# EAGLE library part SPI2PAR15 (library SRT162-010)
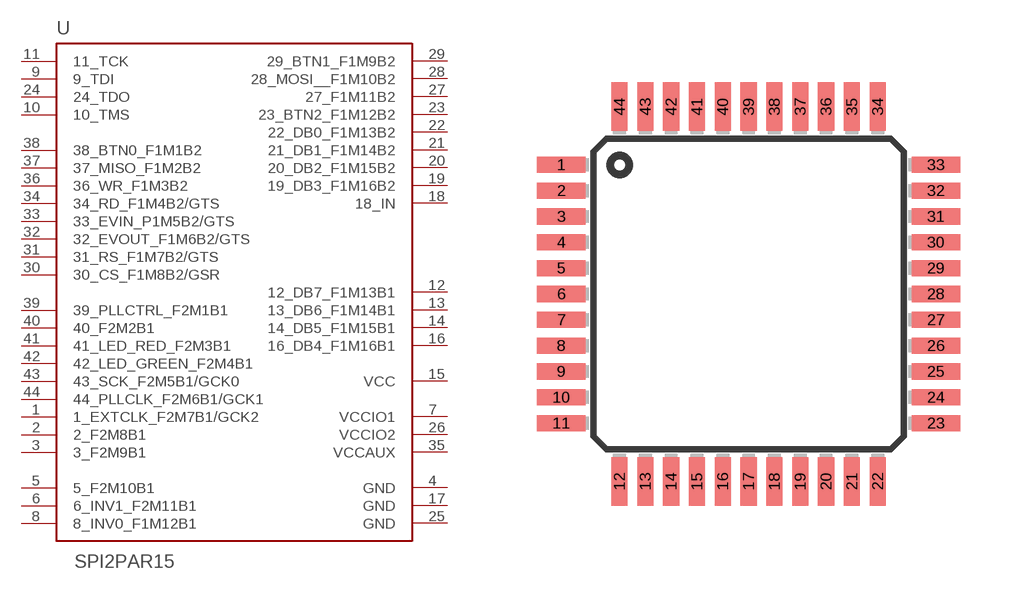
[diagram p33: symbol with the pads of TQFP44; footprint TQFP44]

Designator prefix -

## SPI2PAR15  [TQFP44]
1  1_EXTCLK_F2M7B1/GCK2
2  2_F2M8B1
3  3_F2M9B1
4  GND  pwr
5  5_F2M10B1
6  6_INV1_F2M11B1
7  VCCIO1  pwr
8  8_INV0_F1M12B1
9  9_TDI
10  10_TMS
11  11_TCK  in
12  12_DB7_F1M13B1
13  13_DB6_F1M14B1
14  14_DB5_F1M15B1
15  VCC  pwr
16  16_DB4_F1M16B1
17  GND  pwr
18  18_IN
19  19_DB3_F1M16B2
20  20_DB2_F1M15B2
21  21_DB1_F1M14B2
22  22_DB0_F1M13B2
23  23_BTN2_F1M12B2
24  24_TDO
25  GND  pwr
26  VCCIO2  pwr
27  27_F1M11B2
28  28_MOSI__F1M10B2
29  29_BTN1_F1M9B2
30  30_CS_F1M8B2/GSR
31  31_RS_F1M7B2/GTS
32  32_EVOUT_F1M6B2/GTS
33  33_EVIN_P1M5B2/GTS
34  34_RD_F1M4B2/GTS
35  VCCAUX  pwr
36  36_WR_F1M3B2
37  37_MISO_F1M2B2
38  38_BTN0_F1M1B2
39  39_PLLCTRL_F2M1B1
40  40_F2M2B1
41  41_LED_RED_F2M3B1
42  42_LED_GREEN_F2M4B1
43  43_SCK_F2M5B1/GCK0
44  44_PLLCLK_F2M6B1/GCK1

## Footprint TQFP44 (pad centres in mm)
smd 1.5 x 0.5: 1 -5.8,4; 2 -5.8,3.2; 3 -5.8,2.4; 4 -5.8,1.6; 5 -5.8,0.8; 6 -5.8,0; 7 -5.8,-0.8; 8 -5.8,-1.6; 9 -5.8,-2.4; 10 -5.8,-3.2; 11 -5.8,-4; 23 5.8,-4; 24 5.8,-3.2; 25 5.8,-2.4; 26 5.8,-1.6; 27 5.8,-0.8; 28 5.8,0; 29 5.8,0.8; 30 5.8,1.6; 31 5.8,2.4; 32 5.8,3.2; 33 5.8,4
smd 0.5 x 1.5: 12 -4,-5.8; 13 -3.2,-5.8; 14 -2.4,-5.8; 15 -1.6,-5.8; 16 -0.8,-5.8; 17 0,-5.8; 18 0.8,-5.8; 19 1.6,-5.8; 20 2.4,-5.8; 21 3.2,-5.8; 22 4,-5.8; 34 4,5.8; 35 3.2,5.8; 36 2.4,5.8; 37 1.6,5.8; 38 0.8,5.8; 39 0,5.8; 40 -0.8,5.8; 41 -1.6,5.8; 42 -2.4,5.8; 43 -3.2,5.8; 44 -4,5.8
